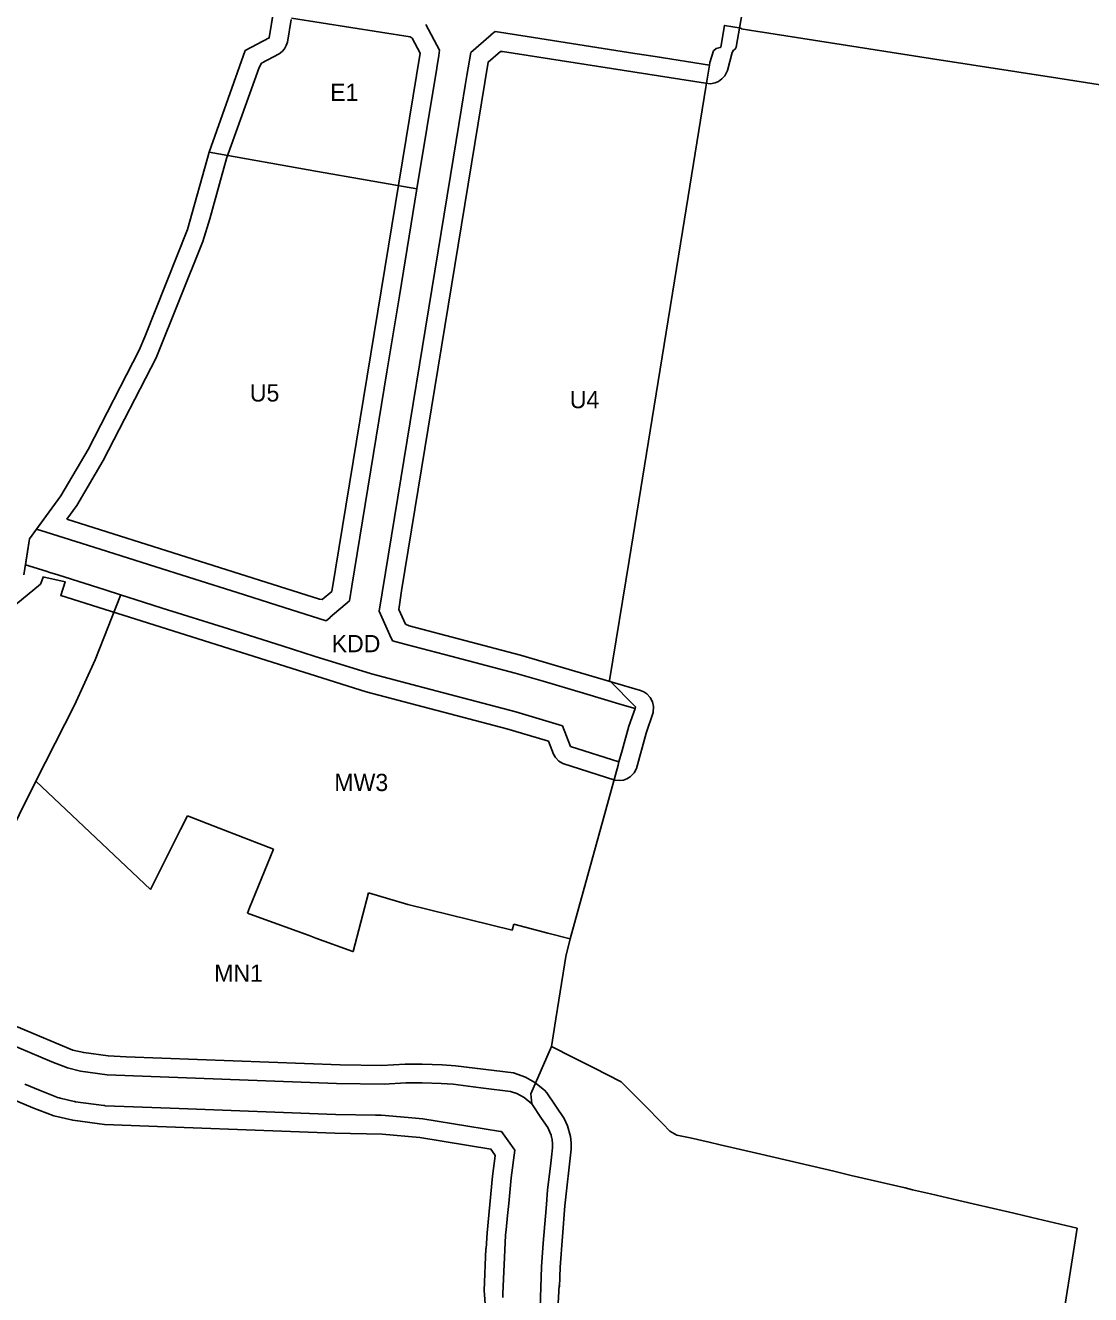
# Model space of a CAD drawing. Extents: x 7428080 to 7432143, y 5545880 to 5549217.
# Drawn here: x 7429567 to 7429909.5, y 5548484.5 to 5548892.7 of the extents above; entities that cross this region are included whole.
import ezdxf

# ---------------------------------------------------------------- set-up
doc = ezdxf.new("R2010")
doc.units = 0
for name, color, linetype in [('CZ_L_granica obszaru objętego planem', 7, 'Continuous'), ('CZ_L_linie rozgraniczające tereny o różnym przeznaczeniu oraz różnych warunkach ich zabudowy i zagospodarowania', 7, 'Continuous'), ('CZ_L_maksymalne nieprzekraczalne linie zabudowy', 7, 'Continuous'), ('CZ_L_opisy_linie rozgraniczające tereny o różnym przeznaczeniu oraz różnych warunkach ich zabudowy i zagospodarowania', 7, 'Continuous')]:
    doc.layers.add(name, color=color, linetype=linetype)

msp = doc.modelspace()

# ---------------------------------------------------------------- linework, layer by layer
at = {"layer": 'CZ_L_granica obszaru objętego planem'}
for p, q in [((7429645.43, 5548888.69), (7429648.99, 5548910.5)), ((7429637.72, 5548884.64), (7429645.43, 5548888.69)), ((7429626.09, 5548851.97), (7429637.72, 5548884.64)), ((7429619.16, 5548827.07), (7429626.09, 5548851.97)), ((7429605.45, 5548792.59), (7429619.16, 5548827.07)), ((7429603.56, 5548788.24), (7429605.45, 5548792.59)), ((7429587.18, 5548756.3), (7429603.56, 5548788.24)), ((7429578.43, 5548741.47), (7429587.18, 5548756.3)), ((7429568.3, 5548727.63), (7429578.43, 5548741.47)), ((7429566.53, 5548715.99), (7429568.3, 5548727.63))]:
    msp.add_line(p, q, dxfattribs=at)
at = {"layer": 'CZ_L_linie rozgraniczające tereny o różnym przeznaczeniu oraz różnych warunkach ich zabudowy i zagospodarowania'}
for p, q in [((7429695.83, 5548893.01), (7429700.21, 5548884.78)), ((7429790.68, 5548885.72), (7429791.76, 5548892.74)), ((7429791.76, 5548892.74), (7429791.74, 5548892.75)), ((7429791.76, 5548892.74), (7429797.15, 5548891.83)), ((7429797.15, 5548891.83), (7429797.13, 5548891.62)), ((7429797.13, 5548891.62), (7429802.52, 5548890.79)), ((7429710.22, 5548884.07), (7429716.74, 5548889.67)), ((7429716.73, 5548889.67), (7429718.08, 5548890.83)), ((7429716.74, 5548889.67), (7429716.73, 5548889.67)), ((7429718.08, 5548890.83), (7429728.35, 5548889.22)), ((7429728.35, 5548889.22), (7429763.03, 5548883.75)), ((7429802.52, 5548890.79), (7429802.64, 5548890.8)), ((7429802.64, 5548890.8), (7429858.01, 5548882.14)), ((7429699.93, 5548883.08), (7429699.28, 5548879.12)), ((7429700.21, 5548884.78), (7429699.93, 5548883.08)), ((7429709, 5548876.59), (7429710.22, 5548884.07)), ((7429763.03, 5548883.75), (7429769.5, 5548882.74)), ((7429787.14, 5548880.77), (7429788.24, 5548884.61)), ((7429788.24, 5548884.61), (7429789.18, 5548885.29)), ((7429789.18, 5548885.29), (7429790.44, 5548885.68)), ((7429790.44, 5548885.68), (7429790.68, 5548885.72)), ((7429699.27, 5548879.03), (7429692.91, 5548840.23)), ((7429699.28, 5548879.12), (7429699.27, 5548879.03)), ((7429769.5, 5548882.74), (7429787.01, 5548880)), ((7429785.84, 5548872.9), (7429787.01, 5548880)), ((7429787.01, 5548880), (7429787.14, 5548880.77)), ((7429858.01, 5548882.14), (7429898.98, 5548875.73)), ((7429708.48, 5548873.43), (7429709, 5548876.59)), ((7429898.98, 5548875.73), (7429982.71, 5548862.61)), ((7429707.28, 5548866.08), (7429708.48, 5548873.43)), ((7429778.92, 5548830.4), (7429785.84, 5548872.9)), ((7429704.71, 5548850.39), (7429707.28, 5548866.08)), ((7429626.11, 5548852.02), (7429660.91, 5548845.75)), ((7429680.8, 5548704.35), (7429704.71, 5548850.39)), ((7429660.91, 5548845.75), (7429692.91, 5548840.23)), ((7429692.91, 5548840.23), (7429687.27, 5548805.75)), ((7429769.17, 5548770.23), (7429778.92, 5548830.4)), ((7429687.27, 5548805.75), (7429683.27, 5548781.34)), ((7429683.27, 5548781.34), (7429671.98, 5548712.37)), ((7429761.13, 5548720.68), (7429769.17, 5548770.23)), ((7429573.72, 5548729.73), (7429570.56, 5548730.72)), ((7429589.04, 5548724.88), (7429573.72, 5548729.73)), ((7429606.66, 5548719.32), (7429589.04, 5548724.88)), ((7429754.87, 5548682.08), (7429761.13, 5548720.68)), ((7429573.67, 5548717.16), (7429567.03, 5548719.26)), ((7429574.92, 5548716.76), (7429573.67, 5548717.16)), ((7429577.41, 5548715.98), (7429574.92, 5548716.76)), ((7429592.65, 5548711.16), (7429577.41, 5548715.98)), ((7429621.55, 5548714.61), (7429606.66, 5548719.32)), ((7429635.11, 5548710.32), (7429621.55, 5548714.61)), ((7429671.98, 5548712.37), (7429671.2, 5548707.62)), ((7429589.51, 5548688.68), (7429597.65, 5548709.39)), ((7429597.65, 5548709.58), (7429592.65, 5548711.16)), ((7429597.65, 5548709.39), (7429597.65, 5548709.58)), ((7429597.65, 5548709.58), (7429605.05, 5548707.24)), ((7429647.84, 5548706.31), (7429635.11, 5548710.32)), ((7429671.2, 5548707.62), (7429664.97, 5548702.37)), ((7429605.05, 5548707.24), (7429611.04, 5548705.35)), ((7429611.04, 5548705.35), (7429632.29, 5548698.64)), ((7429663.75, 5548701.28), (7429647.84, 5548706.31)), ((7429684.23, 5548696.67), (7429680.8, 5548704.35)), ((7429665, 5548702.36), (7429663.75, 5548701.28)), ((7429664.97, 5548702.37), (7429665, 5548702.36)), ((7429632.29, 5548698.64), (7429649.92, 5548693.07)), ((7429685.05, 5548694.79), (7429684.21, 5548696.67)), ((7429684.21, 5548696.67), (7429684.23, 5548696.67)), ((7429649.92, 5548693.07), (7429659.92, 5548689.91)), ((7429689.43, 5548693.64), (7429685.05, 5548694.79)), ((7429701.74, 5548690.41), (7429689.43, 5548693.64)), ((7429582.78, 5548674.16), (7429589.51, 5548688.68)), ((7429659.92, 5548689.91), (7429678.32, 5548684.15)), ((7429717.26, 5548686.35), (7429701.74, 5548690.41)), ((7429678.32, 5548684.15), (7429693.32, 5548680.22)), ((7429724.53, 5548684.45), (7429717.26, 5548686.35)), ((7429733.52, 5548681.81), (7429724.53, 5548684.45)), ((7429693.32, 5548680.22), (7429705.58, 5548677.01)), ((7429746.5, 5548677.94), (7429733.52, 5548681.81)), ((7429763.24, 5548673.57), (7429754.87, 5548682.08)), ((7429705.58, 5548677.01), (7429724.7, 5548671.92)), ((7429758.86, 5548674.25), (7429746.5, 5548677.94)), ((7429570.43, 5548649.63), (7429582.78, 5548674.16)), ((7429724.7, 5548671.92), (7429739.68, 5548667.45)), ((7429763.06, 5548673.06), (7429758.86, 5548674.25)), ((7429761.04, 5548667.34), (7429763.06, 5548673.06)), ((7429763.06, 5548673.06), (7429763.24, 5548673.57)), ((7429739.68, 5548667.45), (7429742.32, 5548660.81)), ((7429758.9, 5548659.54), (7429761.04, 5548667.34)), ((7429742.32, 5548660.81), (7429757.88, 5548655.84)), ((7429757.88, 5548655.84), (7429758.9, 5548659.54)), ((7429750.54, 5548629.21), (7429757.6, 5548654.82)), ((7429757.6, 5548654.82), (7429757.88, 5548655.84)), ((7429559.62, 5548627.96), (7429570.43, 5548649.63)), ((7429589.72, 5548631.45), (7429570.43, 5548649.63)), ((7429619.11, 5548638.53), (7429616.9, 5548634.12)), ((7429629.35, 5548634.57), (7429619.11, 5548638.53)), ((7429616.9, 5548634.12), (7429607.23, 5548614.83)), ((7429646.75, 5548627.85), (7429629.35, 5548634.57)), ((7429589.72, 5548631.44), (7429589.72, 5548631.45)), ((7429607.23, 5548614.83), (7429589.72, 5548631.44)), ((7429639.14, 5548608.94), (7429646.75, 5548627.85)), ((7429742.22, 5548598.99), (7429750.54, 5548629.21)), ((7429677.36, 5548613.74), (7429672.42, 5548594.85)), ((7429690.04, 5548609.96), (7429677.36, 5548613.74)), ((7429723.54, 5548601.73), (7429690.04, 5548609.96)), ((7429638.45, 5548607.2), (7429639.14, 5548608.94)), ((7429641.66, 5548606.02), (7429638.45, 5548607.2)), ((7429658.29, 5548599.98), (7429641.66, 5548606.02)), ((7429724.1, 5548603.7), (7429723.54, 5548601.73)), ((7429735.01, 5548600.8), (7429724.1, 5548603.7)), ((7429660.4, 5548599.21), (7429658.29, 5548599.98)), ((7429672.34, 5548594.87), (7429660.4, 5548599.21)), ((7429742.22, 5548598.97), (7429735.01, 5548600.82)), ((7429735.01, 5548600.82), (7429735.01, 5548600.8)), ((7429740.78, 5548593.25), (7429742.22, 5548598.97)), ((7429742.22, 5548598.97), (7429742.22, 5548598.99)), ((7429672.42, 5548594.85), (7429672.34, 5548594.87)), ((7429738.53, 5548579.22), (7429740.78, 5548593.25)), ((7429737.58, 5548573.25), (7429738.53, 5548579.22)), ((7429736.14, 5548564.31), (7429737.58, 5548573.25)), ((7429575.56, 5548559.42), (7429547.85, 5548571.05)), ((7429729.59, 5548549.08), (7429736.14, 5548564.31)), ((7429743.2, 5548560.76), (7429736.14, 5548564.31)), ((7429749.78, 5548557.45), (7429743.2, 5548560.76)), ((7429580.56, 5548557.42), (7429575.56, 5548559.42)), ((7429584.77, 5548556.43), (7429580.56, 5548557.42)), ((7429593.34, 5548555.27), (7429584.77, 5548556.43)), ((7429758.61, 5548553.01), (7429749.78, 5548557.45)), ((7429566.86, 5548552.23), (7429571.73, 5548550.19)), ((7429667.04, 5548552.46), (7429593.34, 5548555.27)), ((7429682.42, 5548552.18), (7429667.04, 5548552.46)), ((7429689.38, 5548552.68), (7429682.42, 5548552.18)), ((7429694.65, 5548552.68), (7429689.38, 5548552.68)), ((7429700.7, 5548552.44), (7429694.65, 5548552.68)), ((7429704.53, 5548552.19), (7429700.7, 5548552.44)), ((7429711.05, 5548551.37), (7429704.53, 5548552.19)), ((7429766.08, 5548545.43), (7429758.61, 5548553.01)), ((7429571.73, 5548550.19), (7429571.76, 5548550.18)), ((7429571.76, 5548550.18), (7429571.8, 5548550.16)), ((7429571.8, 5548550.16), (7429577.18, 5548548)), ((7429714.28, 5548550.96), (7429711.05, 5548551.37)), ((7429723.01, 5548549.91), (7429714.28, 5548550.96)), ((7429723.37, 5548549.78), (7429723.01, 5548549.91)), ((7429725, 5548549.19), (7429723.37, 5548549.78)), ((7429727.4, 5548547.89), (7429725, 5548549.19)), ((7429729.84, 5548545.9), (7429729.59, 5548549.08)), ((7429577.18, 5548548), (7429577.26, 5548547.98)), ((7429577.26, 5548547.98), (7429577.32, 5548547.94)), ((7429577.32, 5548547.94), (7429577.91, 5548547.77)), ((7429577.91, 5548547.77), (7429578.21, 5548547.7)), ((7429578.21, 5548547.7), (7429582.72, 5548546.64)), ((7429582.72, 5548546.64), (7429582.92, 5548546.62)), ((7429582.92, 5548546.62), (7429583.19, 5548546.55)), ((7429583.19, 5548546.55), (7429592.24, 5548545.33)), ((7429592.24, 5548545.33), (7429592.6, 5548545.31)), ((7429592.6, 5548545.31), (7429592.72, 5548545.29)), ((7429592.72, 5548545.29), (7429601.75, 5548544.94)), ((7429601.75, 5548544.94), (7429616.46, 5548544.38)), ((7429616.46, 5548544.38), (7429666.71, 5548542.46)), ((7429729.84, 5548545.9), (7429727.4, 5548547.89)), ((7429733.01, 5548541.2), (7429729.84, 5548545.9)), ((7429771.75, 5548539.67), (7429766.08, 5548545.43)), ((7429666.71, 5548542.46), (7429666.8, 5548542.46)), ((7429666.8, 5548542.46), (7429666.81, 5548542.46)), ((7429666.81, 5548542.46), (7429679.61, 5548542.23)), ((7429679.61, 5548542.23), (7429681.44, 5548542.2)), ((7429681.44, 5548542.2), (7429690.09, 5548541.47)), ((7429690.09, 5548541.47), (7429694.85, 5548541.02)), ((7429694.85, 5548541.02), (7429709.29, 5548538.68)), ((7429735.01, 5548538.25), (7429733.01, 5548541.2)), ((7429709.29, 5548538.68), (7429719.81, 5548536.98)), ((7429719.81, 5548536.98), (7429720.07, 5548536.94)), ((7429720.07, 5548536.94), (7429724.35, 5548531.02)), ((7429735.69, 5548536.82), (7429735.01, 5548538.25)), ((7429736.03, 5548535.83), (7429735.69, 5548536.82)), ((7429771.97, 5548539.45), (7429771.75, 5548539.67)), ((7429774.24, 5548537.14), (7429771.97, 5548539.45)), ((7429776.48, 5548535.76), (7429774.24, 5548537.14)), ((7429736.23, 5548535.06), (7429736.03, 5548535.83)), ((7429736.25, 5548534.95), (7429736.23, 5548535.06)), ((7429736.37, 5548534.32), (7429736.25, 5548534.95)), ((7429736.29, 5548529.74), (7429736.5, 5548531.85)), ((7429736.49, 5548533.15), (7429736.37, 5548534.32)), ((7429736.5, 5548531.85), (7429736.49, 5548533.15)), ((7429780.73, 5548534.95), (7429776.48, 5548535.76)), ((7429786.91, 5548533.53), (7429780.73, 5548534.95)), ((7429790.45, 5548532.71), (7429786.91, 5548533.53)), ((7429802.09, 5548530.01), (7429790.45, 5548532.71)), ((7429724.35, 5548531.02), (7429723.24, 5548522.07)), ((7429735.83, 5548525.86), (7429736.29, 5548529.74)), ((7429812.74, 5548527.52), (7429802.09, 5548530.01)), ((7429734.94, 5548518.26), (7429735.83, 5548525.86)), ((7429827.01, 5548524.19), (7429812.74, 5548527.52)), ((7429832.59, 5548522.88), (7429827.01, 5548524.19)), ((7429723.24, 5548522.07), (7429722.43, 5548513.8)), ((7429849.85, 5548518.84), (7429832.59, 5548522.88)), ((7429734.54, 5548513.55), (7429734.94, 5548518.26)), ((7429852.28, 5548518.28), (7429849.85, 5548518.84)), ((7429858.08, 5548516.92), (7429852.28, 5548518.28)), ((7429865.29, 5548515.24), (7429858.08, 5548516.92)), ((7429722.43, 5548513.8), (7429722.05, 5548509.96)), ((7429734.23, 5548509.77), (7429734.54, 5548513.55)), ((7429871.79, 5548513.72), (7429865.29, 5548515.24)), ((7429884.79, 5548510.68), (7429871.79, 5548513.72)), ((7429722.05, 5548509.96), (7429721.6, 5548505.33)), ((7429733.53, 5548501.06), (7429734.23, 5548509.77)), ((7429890.68, 5548509.31), (7429884.79, 5548510.68)), ((7429905.2, 5548505.92), (7429890.68, 5548509.31)), ((7429721.42, 5548503.5), (7429720.58, 5548484.92)), ((7429721.44, 5548503.57), (7429721.42, 5548503.5)), ((7429721.6, 5548505.33), (7429721.44, 5548503.76)), ((7429721.44, 5548503.76), (7429721.44, 5548503.57)), ((7429904, 5548498.36), (7429905.2, 5548505.92)), ((7429732.99, 5548493.43), (7429733.53, 5548501.06)), ((7429900.68, 5548477.42), (7429904, 5548498.36)), ((7429732.49, 5548480.24), (7429732.99, 5548493.43)), ((7429720.58, 5548484.92), (7429720.52, 5548483.63))]:
    msp.add_line(p, q, dxfattribs=at)
for points in [[(7429626.11, 5548852.02), (7429637.72, 5548884.64), (7429645.43, 5548888.69), (7429647.59, 5548901.93)], [(7429570.56, 5548730.72), (7429578.43, 5548741.47), (7429587.18, 5548756.3), (7429603.56, 5548788.24), (7429605.45, 5548792.59), (7429619.16, 5548827.07), (7429626.09, 5548851.97), (7429626.11, 5548852.02)], [(7429567.03, 5548719.26), (7429568.3, 5548727.63), (7429570.56, 5548730.72)]]:
    msp.add_lwpolyline(points, dxfattribs=at)
at = {"layer": 'CZ_L_maksymalne nieprzekraczalne linie zabudowy'}
for points in [[(7430360.94, 5548895.1), (7430108.03, 5548935.09), (7429809.17, 5548981.99), (7429800.45, 5548922.62), (7429799.4, 5548912.72), (7429799.29, 5548909.64), (7429799.45, 5548907.98), (7429795.56, 5548885.78)], [(7429580.36, 5548733.92), (7429661.63, 5548708.24), (7429662.48, 5548708.11), (7429665.52, 5548710.68), (7429693.94, 5548883.79), (7429691.34, 5548888.66), (7429690.74, 5548889.07), (7429652.55, 5548895.08)], [(7429652.49, 5548894.69), (7429651.28, 5548887.36), (7429650.92, 5548886.27), (7429650.34, 5548885.24), (7429649.57, 5548884.35), (7429648.63, 5548883.62), (7429642.91, 5548880.59), (7429642.16, 5548879.22), (7429631.74, 5548849.9), (7429626.36, 5548830.55), (7429624.1, 5548823.27), (7429609.05, 5548785.81), (7429592.05, 5548752.77), (7429583.55, 5548738.35), (7429580.37, 5548733.97)], [(7429795.55, 5548885.79), (7429795.23, 5548885.12), (7429794.73, 5548884.73), (7429794.32, 5548884.07), (7429792.76, 5548878.28), (7429791.91, 5548876.53), (7429790.99, 5548875.51), (7429789.89, 5548874.74), (7429788.76, 5548874.26), (7429787.26, 5548874), (7429785.67, 5548874.13), (7429720.42, 5548884.39), (7429719.78, 5548884.37), (7429715.79, 5548880.92), (7429687.94, 5548710.85), (7429687.15, 5548704.85), (7429689.22, 5548700.19), (7429690.39, 5548699.59), (7429726.21, 5548690.21), (7429764.75, 5548678.82), (7429765.86, 5548678.37), (7429766.82, 5548677.73), (7429767.9, 5548676.6), (7429768.67, 5548675.2), (7429769.03, 5548673.64), (7429768.92, 5548671.77), (7429766.66, 5548665.15), (7429763.51, 5548653.79), (7429762.77, 5548652.37), (7429761.43, 5548651.01), (7429760.41, 5548650.4), (7429759.29, 5548650.01), (7429758.07, 5548649.85), (7429756.59, 5548649.99), (7429739.88, 5548655.32), (7429738.55, 5548656.14), (7429737.49, 5548657.25), (7429736.87, 5548658.3), (7429735.19, 5548662.5), (7429734.1, 5548662.86), (7429721.82, 5548666.48), (7429676.61, 5548678.39), (7429578.4, 5548709.37), (7429579.86, 5548713.75), (7429572.69, 5548715.43)], [(7429572.8, 5548715.52), (7429571.94, 5548713.05), (7429534.01, 5548681.96), (7429503.84, 5548660.58), (7429482.42, 5548648.2), (7429454.26, 5548629.06)], [(7429715.23, 5548499.33), (7429715.47, 5548504.35), (7429717.27, 5548522.67), (7429718.08, 5548529.18), (7429718.01, 5548529.54), (7429716.73, 5548531.32), (7429693.9, 5548535.08), (7429681.78, 5548536.15), (7429666.49, 5548536.47), (7429592.48, 5548539.29), (7429582.27, 5548540.62), (7429576.21, 5548542.01), (7429569.46, 5548544.64), (7429539.67, 5548557.14), (7429503.52, 5548573.95), (7429443.6, 5548608.35), (7429441.12, 5548609), (7429437.2, 5548605.98), (7429357.8, 5548506.71), (7429357.6, 5548502.44), (7429357.83, 5548501.41), (7429364.53, 5548490.43), (7429366.81, 5548484.98)], [(7429548.5, 5548577.29), (7429582.33, 5548563.17), (7429585.8, 5548562.35), (7429593.67, 5548561.28), (7429599.39, 5548561.04), (7429668.24, 5548558.44), (7429681.68, 5548558.19), (7429689.15, 5548558.67), (7429694.65, 5548558.68), (7429701.07, 5548558.43), (7429705.28, 5548558.15), (7429723.92, 5548555.84), (7429727.79, 5548554.5), (7429730.88, 5548552.77), (7429733.89, 5548550.32), (7429734.69, 5548549.43), (7429740.27, 5548541.13), (7429741.36, 5548538.77), (7429742.28, 5548535.34), (7429742.49, 5548533.38), (7429742.47, 5548531.3), (7429740.52, 5548513.12), (7429739, 5548493.37), (7429738.75, 5548487)], [(7429617.63, 5548439.11), (7429623.98, 5548440.62), (7429659.34, 5548446.97), (7429679.98, 5548449.94), (7429706.66, 5548453.04), (7429712.54, 5548457.18), (7429714.11, 5548458.63), (7429718.11, 5548465.46), (7429716.07, 5548472.3), (7429714.99, 5548480.18), (7429714.51, 5548485.82), (7429715.05, 5548499.33)], [(7429738.61, 5548487.43), (7429738.34, 5548481.76), (7429739.9, 5548469.67), (7429744.35, 5548460.73), (7429744.82, 5548458.36), (7429744.42, 5548455.96), (7429739.4, 5548449.33), (7429718.28, 5548434.17), (7429714.22, 5548432.23), (7429693.91, 5548429.24), (7429671.73, 5548426.83), (7429655.62, 5548423.79), (7429644.04, 5548420.8)]]:
    msp.add_lwpolyline(points, dxfattribs=at)

# ---------------------------------------------------------------- texts
at = {"layer": 'CZ_L_opisy_linie rozgraniczające tereny o różnym przeznaczeniu oraz różnych warunkach ich zabudowy i zagospodarowania'}
for s, p in [('E1', (7429665.03, 5548868.47)), ('U5', (7429639.19, 5548771.77)), ('U4', (7429742.08, 5548769.62)), ('KDD', (7429665.51, 5548691.14)), ('MW3', (7429666.37, 5548646.48)), ('MN1', (7429627.73, 5548585.15))]:
    msp.add_text(s, height=5.549, dxfattribs=at).set_placement(p)

doc.saveas('drawing.dxf')
